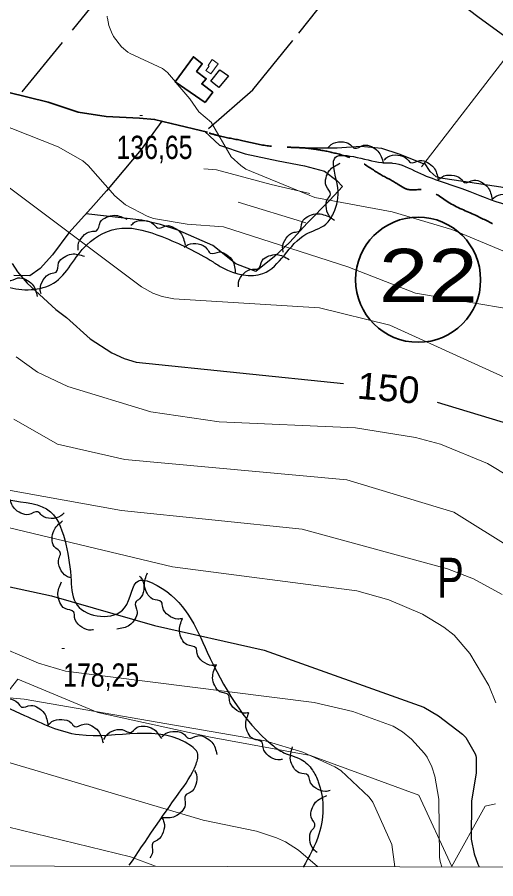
# Model space of a CAD drawing. Extents: x 483840 to 488445, y 4386047 to 4389027.
# Drawn here: x 485197 to 485377.2, y 4386441.2 to 4386765.5 of the extents above; entities that cross this region are included whole.
import ezdxf
from ezdxf.enums import TextEntityAlignment as Align

# ---------------------------------------------------------------- set-up
doc = ezdxf.new("R2010")
doc.units = 0
doc.header["$LTSCALE"] = 4
doc.linetypes.add('LONG_DASHED', pattern=[7.5, 6, -1.5])
for name, color, linetype, lineweight in [('1', 7, 'Continuous', 13), ('13', 7, 'Continuous', 25), ('21', 7, 'Continuous', 25), ('25', 7, 'LONG_DASHED', 25), ('27', 7, 'Continuous', 25), ('47', 7, 'Continuous', 35), ('51', 7, 'Continuous', 13), ('6', 7, 'Continuous', 35), ('7', 7, 'Continuous', 13), ('8', 7, 'Continuous', 25), ('9', 7, 'Continuous', 13)]:
    doc.layers.add(name, color=color, linetype=linetype, lineweight=lineweight)
doc.layers.add('31', color=7, linetype='Continuous')

msp = doc.modelspace()

# ---------------------------------------------------------------- linework, layer by layer
at = {"layer": '1'}
msp.add_lwpolyline([(484110.5, 4388760.3), (487685.8, 4388753.5), (487681.9, 4386441.2), (484105.5, 4386448.1)], close=True, dxfattribs=at)
at = {"layer": '21'}
msp.add_lwpolyline([(485276.56, 4386743.39), (485272.88, 4386739.01), (485269.93, 4386741.35), (485273.32, 4386745.69)], close=True, dxfattribs=at)
at = {"layer": '25'}
for points in [[(485198.79, 4386737.4), (485226.51, 4386771.29), (485272.06, 4386831.1), (485272.36, 4386831.53), (485272.94, 4386830.97)], [(485269.02, 4386723.6), (485285.69, 4386738.1), (485303.06, 4386759.47), (485330.24, 4386793.84)], [(485331.26, 4386793.17), (485353.03, 4386779.17), (485370.43, 4386765.77), (485384.85, 4386755.29)], [(485251.39, 4386726.37), (485243.66, 4386715.72), (485230.61, 4386700.17), (485224.73, 4386693.54), (485216.43, 4386684.31), (485210.3, 4386676.04), (485205.58, 4386670.85), (485201.75, 4386668.11), (485195.68, 4386668.31)], [(485267.64, 4386722.49), (485273.14, 4386717.32), (485282.79, 4386714.11), (485295.3, 4386711.41), (485305.21, 4386709.52), (485312.77, 4386707.48), (485317.37, 4386704.07), (485319.52, 4386701.73), (485314.75, 4386696.62), (485306.18, 4386687.98), (485299.63, 4386680.8), (485293.83, 4386675.44), (485286.86, 4386669.75), (485279.28, 4386672.6), (485270.71, 4386679.55), (485257.44, 4386685.34), (485250.97, 4386687.42), (485243.9, 4386689.12), (485222.82, 4386691.42)], [(485350.06, 4386710.24), (485340.84, 4386713.92), (485334.32, 4386716.13), (485326.4, 4386716.87), (485317.54, 4386716.22), (485305.53, 4386716.23)], [(485410.89, 4386690.21), (485407.79, 4386691.29), (485403.13, 4386692.71), (485395.81, 4386695.14), (485389.68, 4386698.07), (485381.75, 4386701.05), (485379.17, 4386701.48), (485364.93, 4386703.59), (485357.33, 4386704.72), (485354.77, 4386705.44), (485352.46, 4386707.47), (485350.43, 4386710.72)]]:
    msp.add_lwpolyline(points, dxfattribs=at)
at = {"layer": '27'}
for points in [[(485314.02, 4386716.34), (485315.29, 4386717.57), (485318.95, 4386718.58), (485322.48, 4386717.5), (485324.04, 4386716.16), (485327.42, 4386717.28), (485330.36, 4386716.78), (485332.86, 4386715.08), (485334.94, 4386710.57)], [(485015.13, 4386590.84), (485027.76, 4386593.71), (485037.35, 4386577.8), (485040.82, 4386567.98), (485048.33, 4386548.52), (485051.93, 4386542.42), (485065.78, 4386530.18), (485079.67, 4386533.83), (485086.6, 4386539.33), (485101.48, 4386543.78), (485109.67, 4386544.16), (485116.49, 4386555.44), (485120.1, 4386570.04), (485124.68, 4386582.49), (485124.21, 4386594.62), (485123.92, 4386603.5), (485123.37, 4386622.14), (485119.2, 4386628.19), (485112.09, 4386631.28), (485104.83, 4386625.38), (485098.75, 4386624.82), (485087.95, 4386637.59), (485079.13, 4386646.82), (485071.75, 4386653.73), (485066.18, 4386654.09), (485055.25, 4386653.07), (485045.22, 4386654.73), (485050.52, 4386665.94), (485062.71, 4386680.81), (485069.35, 4386682.29), (485082.63, 4386683.4), (485089.41, 4386688.79), (485102.97, 4386701.78), (485105.02, 4386697.45), (485104.33, 4386688.21), (485120.89, 4386678.81), (485128.25, 4386676.99), (485134.94, 4386676.25), (485150.37, 4386675.41), (485165.16, 4386678.57), (485178.66, 4386671.97), (485193.04, 4386664), (485210.65, 4386665.41), (485223.14, 4386679.83), (485236.33, 4386686.06), (485251.43, 4386682.92), (485270.74, 4386673.36), (485274.43, 4386671.16), (485289.51, 4386668.96), (485305.71, 4386683.8), (485313.22, 4386687.61), (485316.08, 4386691.69), (485317.71, 4386701.32), (485316.44, 4386712.22), (485334.26, 4386710.77), (485336.63, 4386710.63), (485338.32, 4386710.59), (485347.76, 4386707.14), (485365.47, 4386700.63), (485381.55, 4386694.91), (485400.73, 4386685.96), (485400.91, 4386679.52), (485391.53, 4386668.6), (485390.32, 4386658.6), (485391.27, 4386652.82), (485397.13, 4386640.34), (485408.07, 4386632.92), (485428.48, 4386635.34), (485434.07, 4386636.48), (485441.35, 4386635.8), (485446.26, 4386637.47), (485448.07, 4386639.03)], [(485335.19, 4386711.81), (485336.57, 4386712.93), (485340.3, 4386713.62), (485343.72, 4386712.23), (485345.16, 4386710.76), (485348.62, 4386711.58), (485351.51, 4386710.82), (485353.85, 4386708.91), (485355.53, 4386704.24)], [(485316.46, 4386688.95), (485315.02, 4386690), (485313.42, 4386693.44), (485313.91, 4386697.1), (485314.96, 4386698.86), (485313.3, 4386702.01), (485313.3, 4386704.99), (485314.56, 4386707.74), (485318.65, 4386710.54)], [(485355.51, 4386704.2), (485356.88, 4386705.33), (485360.6, 4386706.06), (485364.04, 4386704.71), (485365.49, 4386703.27), (485368.95, 4386704.12), (485371.84, 4386703.4), (485374.2, 4386701.52), (485375.94, 4386696.87)], [(485376.02, 4386697.08), (485377.41, 4386698.17), (485381.16, 4386698.79), (485384.55, 4386697.34), (485385.97, 4386695.85), (485389.44, 4386696.61), (485392.32, 4386695.8), (485394.62, 4386693.85), (485396.22, 4386689.15)], [(485219.96, 4386677.81), (485219.9, 4386679.59), (485221.62, 4386682.97), (485224.79, 4386684.86), (485226.83, 4386685.12), (485228.27, 4386688.37), (485230.62, 4386690.21), (485233.56, 4386690.92), (485238.29, 4386689.43)], [(485297.19, 4386677.02), (485296.94, 4386678.77), (485298.28, 4386682.32), (485301.24, 4386684.54), (485303.24, 4386685.01), (485304.33, 4386688.4), (485306.46, 4386690.48), (485309.31, 4386691.5), (485314.17, 4386690.53)], [(485239.81, 4386687.15), (485241.18, 4386688.28), (485244.91, 4386688.99), (485248.34, 4386687.62), (485249.79, 4386686.17), (485253.24, 4386687.01), (485256.14, 4386686.27), (485258.49, 4386684.37), (485260.2, 4386679.71)], [(485259.88, 4386678.95), (485261.38, 4386679.9), (485265.17, 4386680.13), (485268.4, 4386678.35), (485269.65, 4386676.72), (485273.19, 4386677.12), (485275.96, 4386676.02), (485278.06, 4386673.84), (485279.17, 4386669.01)], [(485205.93, 4386661.31), (485205.61, 4386663.06), (485206.8, 4386666.66), (485209.65, 4386669), (485211.63, 4386669.56), (485212.57, 4386672.99), (485214.62, 4386675.16), (485217.42, 4386676.3), (485222.32, 4386675.54)], [(485280.31, 4386663.94), (485280.36, 4386665.71), (485282.3, 4386668.98), (485285.59, 4386670.65), (485287.64, 4386670.77), (485289.29, 4386673.92), (485291.76, 4386675.61), (485294.74, 4386676.12), (485299.36, 4386674.32)], [(485183.83, 4386666.88), (485185.14, 4386668.07), (485188.83, 4386668.95), (485192.32, 4386667.74), (485193.84, 4386666.36), (485197.25, 4386667.36), (485200.18, 4386666.76), (485202.61, 4386664.97), (485204.54, 4386660.4)], [(485239.18, 4386446.27), (485257.85, 4386473.42), (485264.33, 4386484.38), (485264.83, 4386488.62), (485262.58, 4386491.11), (485220.26, 4386495.34), (485199.84, 4386502.57), (485143.57, 4386527.98), (485132.12, 4386535.95), (485130.62, 4386539.68), (485134.11, 4386543.67), (485172.95, 4386564.1), (485178.43, 4386574.06), (485178.43, 4386580.29), (485182.41, 4386584.02), (485193.86, 4386583.78), (485209.55, 4386579.29), (485215.28, 4386567.09), (485217.27, 4386553.39), (485219.51, 4386544.17), (485237.44, 4386543.17), (485242.67, 4386553.39), (485249.64, 4386551.64), (485268.56, 4386526.48), (485292.96, 4386491.61), (485297.44, 4386488.62), (485303.92, 4386486.13), (485308.15, 4386482.14), (485310.39, 4386477.66), (485312.13, 4386468.69), (485310.64, 4386457.98), (485304.66, 4386445.52)], [(485214.69, 4386578.96), (485213.4, 4386577.75), (485209.72, 4386576.81), (485206.21, 4386577.96), (485204.68, 4386579.32), (485201.28, 4386578.27), (485198.35, 4386578.83), (485195.88, 4386580.58), (485193.89, 4386585.12)], [(485217.17, 4386554.43), (485215.53, 4386555.09), (485213.13, 4386558.03), (485212.69, 4386561.7), (485213.27, 4386563.66), (485210.89, 4386566.3), (485210.15, 4386569.19), (485210.7, 4386572.17), (485213.97, 4386575.89)], [(485243.06, 4386555.1), (485244.11, 4386553.66), (485244.61, 4386549.9), (485243.05, 4386546.56), (485241.51, 4386545.19), (485242.16, 4386541.69), (485241.26, 4386538.85), (485239.23, 4386536.61), (485234.48, 4386535.16)], [(485259.22, 4386539.17), (485257.46, 4386538.95), (485253.94, 4386540.36), (485251.77, 4386543.35), (485251.33, 4386545.36), (485247.96, 4386546.5), (485245.92, 4386548.67), (485244.95, 4386551.54), (485246.01, 4386556.39)], [(485225.76, 4386534.94), (485223.99, 4386534.82), (485220.56, 4386536.44), (485218.58, 4386539.55), (485218.26, 4386541.58), (485214.97, 4386542.93), (485213.05, 4386545.22), (485212.26, 4386548.14), (485213.6, 4386552.91)], [(485272.07, 4386521.7), (485270.31, 4386521.52), (485266.81, 4386523), (485264.72, 4386526.03), (485264.32, 4386528.05), (485260.97, 4386529.27), (485258.97, 4386531.48), (485258.07, 4386534.36), (485259.22, 4386539.19)], [(485284.13, 4386503.67), (485282.36, 4386503.55), (485278.92, 4386505.15), (485276.93, 4386508.26), (485276.6, 4386510.28), (485273.31, 4386511.62), (485271.38, 4386513.9), (485270.58, 4386516.82), (485271.91, 4386521.6)], [(485188.65, 4386507.41), (485190.08, 4386508.45), (485193.84, 4386508.94), (485197.18, 4386507.38), (485198.55, 4386505.84), (485202.05, 4386506.48), (485204.89, 4386505.57), (485207.13, 4386503.54), (485208.56, 4386498.79)], [(485296.89, 4386486.13), (485295.13, 4386485.96), (485291.65, 4386487.48), (485289.59, 4386490.55), (485289.21, 4386492.56), (485285.89, 4386493.82), (485283.91, 4386496.06), (485283.04, 4386498.96), (485284.26, 4386503.77)], [(485208.72, 4386499.19), (485210.05, 4386500.36), (485213.76, 4386501.17), (485217.23, 4386499.89), (485218.71, 4386498.48), (485222.15, 4386499.41), (485225.06, 4386498.76), (485227.46, 4386496.92), (485229.3, 4386492.31)], [(485229.62, 4386493.56), (485230.49, 4386495.1), (485233.71, 4386497.1), (485237.41, 4386497.06), (485239.28, 4386496.23), (485242.2, 4386498.26), (485245.17, 4386498.61), (485248.05, 4386497.69), (485251.32, 4386493.96)], [(485251.53, 4386494.63), (485252.85, 4386495.82), (485256.55, 4386496.68), (485260.03, 4386495.45), (485261.54, 4386494.06), (485264.96, 4386495.03), (485267.88, 4386494.42), (485270.3, 4386492.61), (485272.2, 4386488.03)], [(485314.8, 4386474.37), (485313.06, 4386474.05), (485309.46, 4386475.27), (485307.15, 4386478.14), (485306.6, 4386480.12), (485303.18, 4386481.09), (485301.02, 4386483.15), (485299.9, 4386485.96), (485300.7, 4386490.86)], [(485263.76, 4386482.01), (485264.51, 4386480.41), (485264.26, 4386476.62), (485262.08, 4386473.64), (485260.31, 4386472.6), (485260.26, 4386469.05), (485258.82, 4386466.43), (485256.39, 4386464.63), (485251.46, 4386464.14)], [(485309.91, 4386451.13), (485308.56, 4386452.28), (485307.21, 4386455.83), (485307.95, 4386459.45), (485309.13, 4386461.13), (485307.7, 4386464.38), (485307.91, 4386467.36), (485309.37, 4386470.01), (485313.65, 4386472.51)], [(485251.47, 4386464.14), (485252.22, 4386462.53), (485251.97, 4386458.75), (485249.79, 4386455.77), (485248.02, 4386454.73), (485247.97, 4386451.18), (485246.95, 4386449.1)]]:
    msp.add_spline(points, degree=3, dxfattribs=at)
at = {"layer": '47'}
msp.add_lwpolyline([(485267.8, 4386733.43), (485256.48, 4386741.12), (485263.36, 4386750.59), (485266.67, 4386747.96), (485264.52, 4386745.08), (485268.18, 4386742.35), (485266.49, 4386740.36), (485270.62, 4386737.25)], close=True, dxfattribs=at)
at = {"layer": '47', "lineweight": 13}
msp.add_lwpolyline([(485272.72, 4386747.91), (485269.84, 4386744.21), (485268.02, 4386745.4), (485269.25, 4386747.04), (485268.91, 4386747.33), (485270.37, 4386749.54)], close=True, dxfattribs=at)
at = {"layer": '51'}
for p, q in [((485399.79, 4386774.64), (485349.23, 4386709.17)), ((485280.21, 4386695.89), (485305.66, 4386688.11))]:
    msp.add_line(p, q, dxfattribs=at)
for points in [[(485307.21, 4386699.13), (485292.58, 4386702.46), (485272.04, 4386708.01), (485267.32, 4386708.39)], [(485307.42, 4386487.57), (485269.8, 4386494.52), (485227.33, 4386503.74), (485197.17, 4386516.32), (485160.61, 4386470.18), (485142.2, 4386446.1)], [(485360.63, 4386445.86), (485348.2, 4386472.7), (485307.42, 4386487.57)], [(485377.13, 4386469.36), (485373.28, 4386468.52), (485360.52, 4386445.68)]]:
    msp.add_lwpolyline(points, dxfattribs=at)
at = {"layer": '6'}
msp.add_lwpolyline([(485115.8, 4386749.57), (485116.23, 4386749.1), (485119.88, 4386748.84), (485125.2, 4386748.79), (485131.48, 4386748.94), (485148.96, 4386747.36), (485165.08, 4386743.99), (485193.34, 4386737.28), (485208.6, 4386733.52), (485219.97, 4386729.79), (485230.45, 4386728.1), (485243, 4386727.43), (485248.7, 4386726.99), (485255.02, 4386725.5), (485268.69, 4386722.23)], dxfattribs=at)
msp.add_circle((485347.99, 4386666.67), 23.55, dxfattribs=at)
at = {"layer": '6', "linetype": 'LONG_DASHED'}
msp.add_spline([(485269.25, 4386721.86), (485273.58, 4386720.69), (485281.99, 4386718.99), (485291.13, 4386717.08), (485298.97, 4386716.54), (485306.16, 4386716.18), (485311.27, 4386715.46), (485318.78, 4386713.76), (485326.94, 4386710.61), (485333.63, 4386706.4), (485340.32, 4386702.69), (485343.71, 4386700.79), (485350.33, 4386700.57), (485359.32, 4386695.9), (485369.58, 4386690.94), (485377.37, 4386687.13), (485386.17, 4386683.79), (485392.17, 4386682.32), (485402.4, 4386678.62), (485406.74, 4386675.4), (485420.48, 4386668.69), (485428.53, 4386664.29), (485438.68, 4386657.3), (485441.05, 4386655.72), (485448.83, 4386650.03), (485458.08, 4386641.35), (485464.26, 4386632.88), (485469.2, 4386623.92), (485470.98, 4386618.97), (485477.37, 4386612.21), (485481.67, 4386606.48), (485480.65, 4386601.56), (485480.95, 4386599.19), (485486.47, 4386592.56), (485492.66, 4386586.48)], degree=3, dxfattribs=at)
at = {"layer": '7'}
for p, q in [((485243.15, 4386728.49), (485244.15, 4386728.49)), ((485213.78, 4386527.87), (485214.78, 4386527.87))]:
    msp.add_line(p, q, dxfattribs=at)
at = {"layer": '8'}
for points in [[(485195.09, 4386672.79), (485197.09, 4386669.67), (485200.76, 4386665.36), (485211.45, 4386655.46), (485215.57, 4386652.45), (485224.43, 4386644.41), (485232.58, 4386639.14), (485237.27, 4386637.02), (485241.74, 4386635.66), (485319.89, 4386627.67)], [(485355.15, 4386620.54), (485387.11, 4386610.95)], [(485188.28, 4386552.39), (485209.83, 4386547.75), (485248.63, 4386536.47), (485289.96, 4386527.21), (485350.19, 4386505.81), (485355.71, 4386502.55), (485364.71, 4386495.6), (485365.92, 4386494.36), (485369.42, 4386488.26), (485369.68, 4386487.45), (485369.81, 4386486.9), (485369.82, 4386480.99), (485368.1, 4386470.58), (485367.93, 4386456.15), (485369.15, 4386450.55), (485370.46, 4386446.71), (485370.46, 4386446.7), (485370.94, 4386445.66)]]:
    msp.add_lwpolyline(points, dxfattribs=at)
at = {"layer": '9'}
msp.add_line((485253.58, 4386744.66), (485256.53, 4386741.2), dxfattribs=at)
for points in [[(485230.8, 4386765.85), (485230.84, 4386765.35), (485230.93, 4386765.11), (485231.51, 4386762.33), (485232.43, 4386759.83), (485233.26, 4386758.19), (485236.28, 4386754.3), (485238.61, 4386752.34), (485239.47, 4386751.78), (485251.69, 4386746.13), (485253.58, 4386744.66)], [(485149.08, 4386741.63), (485212.43, 4386716.72), (485221.67, 4386711.4), (485223.64, 4386709.72), (485233.74, 4386698.29), (485237.75, 4386694.87), (485245.97, 4386690.6), (485248.29, 4386689.74), (485260.97, 4386687.6), (485274.73, 4386686.63), (485321.55, 4386671.49), (485347.03, 4386661.56), (485403.59, 4386652.04)], [(485256.77, 4386740.92), (485262.05, 4386734.74), (485265.37, 4386729.92), (485270.12, 4386725.86), (485270.15, 4386725.78), (485277.53, 4386712.88), (485281.14, 4386709.65), (485283.12, 4386708.25), (485309.09, 4386697.59), (485338.2, 4386692.18), (485360.66, 4386685.6), (485427.62, 4386657.61)], [(485420.75, 4386611.66), (485337.39, 4386649.59), (485310.78, 4386656.07), (485256.02, 4386659.45), (485251.63, 4386660.34), (485248.08, 4386661.59), (485243.8, 4386664.06), (485190.36, 4386703.96)], [(485391.16, 4386587.16), (485374.16, 4386597.46), (485356.42, 4386604.83), (485347.04, 4386607.35), (485324.43, 4386610.88), (485273.1, 4386613.24), (485247.27, 4386617), (485216.06, 4386626.51), (485204.63, 4386631.88), (485196.63, 4386637.7)], [(485195.72, 4386614.22), (485212.19, 4386604.82), (485237.47, 4386599.03)], [(485237.47, 4386599.03), (485321.08, 4386591.34), (485361.46, 4386579.14), (485384.22, 4386565.05)], [(485377.25, 4386507.43), (485374.64, 4386513.93), (485367.51, 4386525.96), (485361.57, 4386532.93), (485357.67, 4386535.95), (485349.61, 4386540.83), (485336.91, 4386546.23), (485324.96, 4386549.53), (485255.49, 4386558.56), (485138.35, 4386586.58)], [(485185.31, 4386588.97), (485236.25, 4386579.77), (485304.3, 4386572.8), (485359.08, 4386557.91), (485368.88, 4386554.09), (485379.69, 4386548.21)], [(485186.65, 4386530.15), (485205, 4386522.33), (485215.13, 4386519.29), (485308.81, 4386507.59), (485323.37, 4386504.18), (485338.55, 4386498.6), (485342.08, 4386496.51), (485345.47, 4386493.79), (485350.37, 4386488.4), (485351.35, 4386486.97), (485353.14, 4386483.29), (485354.32, 4386479.82), (485355.78, 4386471.19), (485356, 4386449.33), (485356.24, 4386447.68), (485356.88, 4386445.69)], [(485072.6, 4386446.23), (485055.7, 4386488.67), (485051.67, 4386503.61), (485051.5, 4386507.01), (485051.56, 4386507.91), (485051.68, 4386508.5), (485051.8, 4386508.85), (485052.11, 4386509.55), (485052.5, 4386510.2), (485052.75, 4386510.5), (485053.24, 4386510.92), (485053.84, 4386511.24), (485055.1, 4386511.68), (485057.08, 4386511.96), (485062.32, 4386511.97), (485118.95, 4386493.51), (485184.05, 4386487.88), (485267, 4386463.21), (485287.1, 4386459.16), (485294.64, 4386456.64), (485298.01, 4386455.12), (485302.88, 4386451.99), (485310.14, 4386445.78)], [(485148.57, 4386513.39), (485199.63, 4386508.84), (485290.38, 4386493.06), (485304.5, 4386488.88), (485316.65, 4386483.32), (485318.93, 4386481.9), (485329.54, 4386471.97), (485330.91, 4386470.02), (485338.03, 4386454.13), (485339.23, 4386445.72)], [(485077.44, 4386446.22), (485069.14, 4386471.64), (485067.73, 4386474.66), (485067.49, 4386475.54), (485067.35, 4386476.69), (485067.35, 4386476.84), (485067.42, 4386477.74), (485067.56, 4386478.34), (485067.63, 4386478.49), (485067.72, 4386478.63), (485068.14, 4386479.06), (485068.84, 4386479.57), (485070.7, 4386480.11), (485072.02, 4386480.34), (485072.03, 4386480.34), (485076.39, 4386480.53), (485087.91, 4386479.06), (485091.2, 4386478.26), (485117.4, 4386468.18), (485125.33, 4386466.15), (485187.99, 4386462.01), (485239.63, 4386449.44), (485249.09, 4386445.89)]]:
    msp.add_lwpolyline(points, dxfattribs=at)

# ---------------------------------------------------------------- texts
at = {"layer": '13', "width": 1.25}
msp.add_text('22', height=20, dxfattribs=at).set_placement((485351.82, 4386658.31), align=Align.CENTER)
at = {"layer": '31', "width": 0.75}
msp.add_text('P', height=15, dxfattribs=at).set_placement((485360.16, 4386547), align=Align.CENTER)
at = {"layer": '7', "width": 0.8}
for s, p in [('136,65', (485234.37, 4386712.13)), ('178,25', (485214.28, 4386513.5))]:
    msp.add_text(s, height=8.75, dxfattribs=at).set_placement(p)
at = {"layer": '8', "width": 1.05}
msp.add_text('150', height=9.999, rotation=355.09, dxfattribs=at).set_placement((485336.38, 4386620.95), align=Align.CENTER)

doc.saveas('drawing.dxf')
